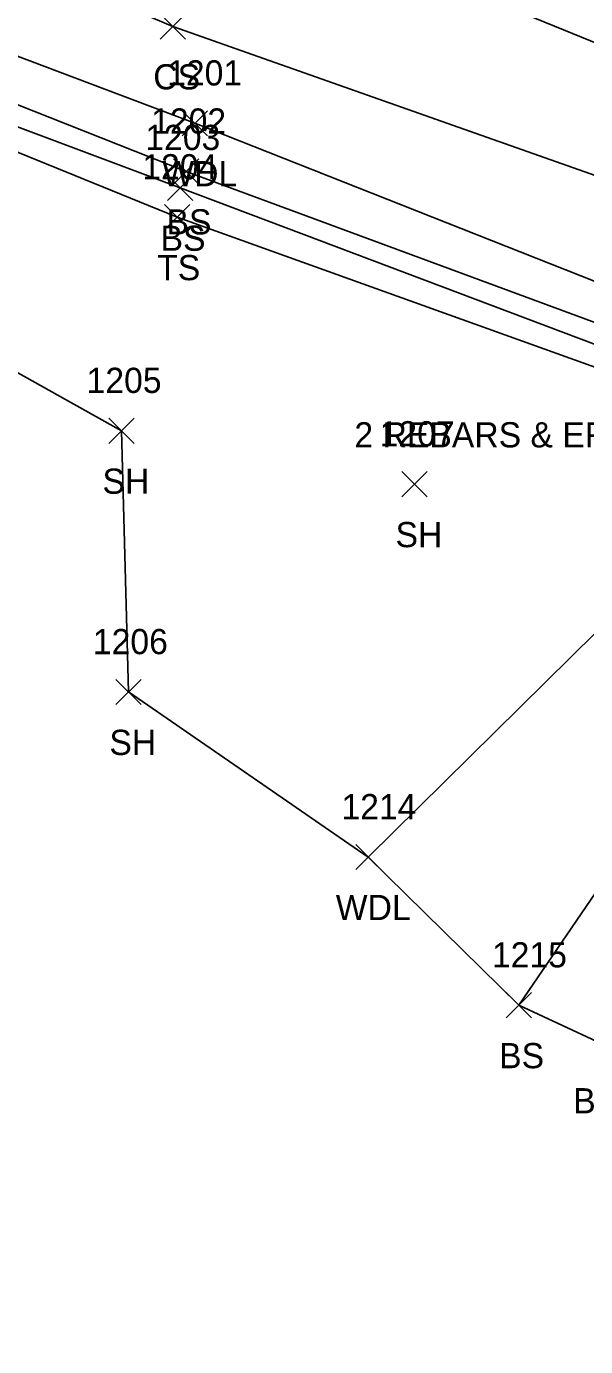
# Model space of a CAD drawing. Extents: x 1547013 to 1549434, y 267998 to 268739.
# Drawn here: x 1548467.5 to 1548511.9, y 268003.2 to 268107.9 of the extents above; entities that cross this region are included whole.
import ezdxf

# ---------------------------------------------------------------- set-up
doc = ezdxf.new("R2010")
doc.units = 0
for name, color, linetype in [('L_A', 7, 'Continuous'), ('L_I', 7, 'Continuous'), ('L_TIC', 7, 'Continuous'), ('LAWA', 7, 'Continuous'), ('LELB', 7, 'Continuous'), ('LSOGP', 7, 'Continuous'), ('M_C', 7, 'Continuous')]:
    doc.layers.add(name, color=color, linetype=linetype)

msp = doc.modelspace()

# ---------------------------------------------------------------- linework, layer by layer
at = {"layer": 'L_TIC'}
for points in [[(1548478.13, 268106.94), (1548480.13, 268108.94)], [(1548480.13, 268106.94), (1548478.13, 268108.94)], [(1548479.87, 268099.25), (1548481.87, 268101.25)], [(1548481.87, 268099.25), (1548479.87, 268101.25)], [(1548479.18, 268095.43), (1548481.18, 268097.43)], [(1548481.18, 268095.43), (1548479.18, 268097.43)], [(1548478.71, 268094.13), (1548480.71, 268096.13)], [(1548480.71, 268094.13), (1548478.71, 268096.13)], [(1548478.47, 268091.8), (1548480.47, 268093.8)], [(1548480.47, 268091.8), (1548478.47, 268093.8)], [(1548474.05, 268074.85), (1548476.05, 268076.85)], [(1548476.05, 268074.85), (1548474.05, 268076.85)], [(1548497.3, 268070.61), (1548499.3, 268072.61)], [(1548499.3, 268070.61), (1548497.3, 268072.61)], [(1548474.61, 268054.12), (1548476.61, 268056.12)], [(1548476.61, 268054.12), (1548474.61, 268056.12)], [(1548493.63, 268041.02), (1548495.63, 268043.02)], [(1548495.63, 268041.02), (1548493.63, 268043.02)], [(1548505.57, 268029.26), (1548507.57, 268031.26)], [(1548507.57, 268029.26), (1548505.57, 268031.26)]]:
    msp.add_lwpolyline(points, dxfattribs=at)
at = {"layer": 'LAWA'}
for points in [[(1548421.13, 268144.61), (1548415.52, 268137.54), (1548414.05, 268129.03), (1548450.89, 268111.62), (1548480.87, 268100.25), (1548525.53, 268082.58), (1548525.56, 268079.65), (1548525.1, 268077.98), (1548524.33, 268076.7), (1548514.72, 268061.84), (1548494.63, 268042.02)], [(1548421.13, 268144.61), (1548456.38, 268129.21), (1548489.15, 268116.23), (1548515.82, 268105.35), (1548565.81, 268089.46), (1548595.41, 268078.87)]]:
    msp.add_lwpolyline(points, dxfattribs=at)
at = {"layer": 'LELB'}
for points in [[(1548289.24, 268200.12), (1548292.11, 268199.39), (1548293.23, 268192.21), (1548309.74, 268172.03), (1548335.42, 268162.83), (1548365.1, 268153.15), (1548400.46, 268134.44), (1548414.42, 268125.58), (1548450.52, 268108.18), (1548480.18, 268096.43), (1548525.56, 268079.65), (1548533.49, 268078.22), (1548538.36, 268080.07), (1548548.83, 268079.87)], [(1548289.24, 268200.12), (1548291.1, 268191.14), (1548308.71, 268170.17), (1548334.15, 268160.77), (1548364.93, 268151.69), (1548400.57, 268132.64), (1548414.23, 268124.12), (1548450.61, 268106.02), (1548479.71, 268095.13), (1548525.1, 268077.98), (1548532.42, 268076.13)], [(1548306.43, 268199.29), (1548321.43, 268192.43), (1548332.78, 268181.9), (1548367.71, 268165.7), (1548391.94, 268148.16), (1548415.52, 268137.54), (1548452.83, 268119.09), (1548479.13, 268107.94), (1548530.85, 268089.69)], [(1548450.66, 268104.52), (1548479.47, 268092.8), (1548524.33, 268076.7)], [(1548506.57, 268030.26), (1548522.56, 268053.68), (1548532.42, 268076.13), (1548533.49, 268078.22)]]:
    msp.add_lwpolyline(points, dxfattribs=at)
at = {"layer": 'LSOGP'}
msp.add_lwpolyline([(1548448.23, 268090.84), (1548475.05, 268075.85), (1548475.61, 268055.12), (1548494.63, 268042.02), (1548506.57, 268030.26), (1548514.3, 268026.68), (1548515.43, 268025.99), (1548520.54, 268019.12), (1548523.56, 268016.08), (1548532.99, 268010.68), (1548542.3, 268026), (1548565.76, 268021.3), (1548592.57, 268010.46), (1548617.71, 268005.03), (1548631.11, 268003.17), (1548635.64, 268007.75), (1548640.17, 268012.32), (1548644.7, 268016.9), (1548649.22, 268021.48), (1548666.42, 268022.87), (1548707.91, 268010.05)], dxfattribs=at)

# ---------------------------------------------------------------- texts
at = {"layer": 'L_A'}
for s, p in [('CS', (1548477.57, 268102.94)), ('WDL', (1548478.29, 268095.25)), ('BS', (1548478.62, 268091.43)), ('BS', (1548478.15, 268090.13)), ('TS', (1548477.88, 268087.8)), ('SH', (1548473.54, 268070.85)), ('SH', (1548496.79, 268066.61)), ('SH', (1548474.09, 268050.12)), ('WDL', (1548492.05, 268037.02)), ('BS', (1548505.01, 268025.26)), ('BRKR', (1548510.89, 268021.68))]:
    msp.add_text(s, height=2, dxfattribs=at).set_placement(p)
at = {"layer": 'L_I'}
for s, p in [('1201', (1548478.67, 268103.25)), ('1202', (1548477.4, 268099.43)), ('1203', (1548476.94, 268098.13)), ('1204', (1548476.7, 268095.8)), ('1205', (1548472.28, 268078.85)), ('1207', (1548495.53, 268074.61)), ('1206', (1548472.78, 268058.12)), ('1214', (1548492.5, 268045.02)), ('1215', (1548504.44, 268033.26))]:
    msp.add_text(s, height=2, dxfattribs=at).set_placement(p)
at = {"layer": 'M_C'}
msp.add_text('2 REBARS & ERODED CONCRETE POOR', height=2, dxfattribs=at).set_placement((1548493.53, 268074.53))

doc.saveas('drawing.dxf')
